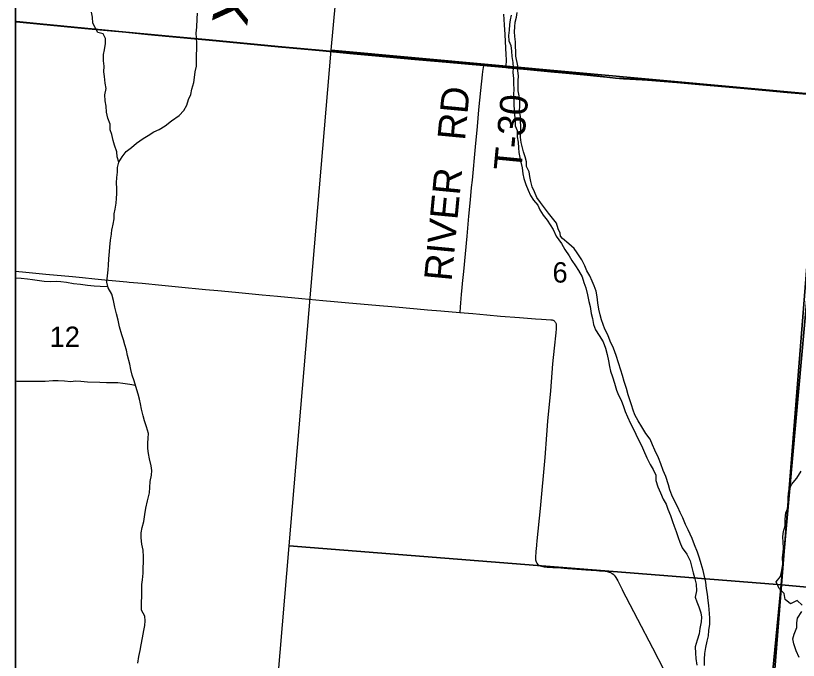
# Model space of a CAD drawing. Extents: x 0 to 1067, y 0 to 440.
# Drawn here: x 131 to 227.4, y 122 to 201.4 of the extents above; entities that cross this region are included whole.
import ezdxf

# ---------------------------------------------------------------- set-up
doc = ezdxf.new("R2010")
doc.units = 0
for name, color, linetype in [('GM_X_County_Road', 7, 'Continuous'), ('GM_X_Major_River', 7, 'Continuous'), ('GM_X_Minor_River', 7, 'Continuous'), ('GM_X_Minor_River_Text', 7, 'Continuous'), ('GM_X_Section', 7, 'Continuous'), ('GM_X_Section_Text', 7, 'Continuous'), ('GM_X_Township_Road', 7, 'Continuous'), ('GM_X_Township_Road_Text', 7, 'Continuous'), ('SH_Text', 7, 'Continuous')]:
    doc.layers.add(name, color=color, linetype=linetype)

msp = doc.modelspace()

# ---------------------------------------------------------------- linework, layer by layer
at = {"layer": 'GM_X_County_Road'}
msp.add_line((188.622, 195.247), (191.362, 194.993), dxfattribs=at)
for points in [[(131, 200.649), (131.123, 200.637), (134.011, 200.355), (139.505, 199.822), (144.57, 199.339), (147.273, 199.083), (149.897, 198.836), (154.854, 198.372), (163.342, 197.554), (166.563, 197.26), (168.841, 197.045), (172.18, 196.73), (174.869, 196.474), (180.185, 196), (184.009, 195.651), (188.622, 195.247)], [(191.362, 194.993), (191.676, 194.964), (194.011, 194.748), (196.906, 194.477), (198.761, 194.306), (200.985, 194.088), (202.579, 193.925), (204.214, 193.751), (204.904, 193.672), (205.881, 193.593), (208.153, 193.47), (208.821, 193.431), (212.462, 193.133), (214.727, 192.933), (218.886, 192.563), (221.634, 192.321), (226.053, 191.924), (227.501, 191.802), (229.802, 191.593), (230.708, 191.509)]]:
    msp.add_lwpolyline(points, dxfattribs=at)
at = {"layer": 'GM_X_Major_River'}
for points in [[(198.12, 174.21), (198.064, 174.582), (197.845, 175.14), (197.604, 175.813), (197.144, 176.421), (196.616, 177.054), (196.134, 177.709), (195.63, 178.387), (195.193, 178.994), (194.916, 179.665), (194.616, 180.292), (194.453, 180.936), (194.334, 181.557), (194.26, 182.153), (193.938, 182.803), (193.933, 183.397), (193.745, 183.997), (193.558, 184.62), (193.273, 185.771), (193.201, 186.413), (193.244, 187.12), (193.218, 187.783), (193.167, 188.379), (193.185, 188.972), (193.067, 189.616), (193.086, 190.278), (193.083, 190.941), (193.008, 191.514), (192.912, 192.111), (192.886, 192.775), (192.88, 193.346), (192.943, 193.961), (192.871, 194.603), (192.843, 195.221), (192.605, 196.416), (192.599, 196.987), (192.571, 197.582), (192.588, 198.153), (192.493, 198.819), (192.464, 199.391), (192.483, 200.03), (192.522, 200.6), (192.676, 201.189), (192.784, 201.78)], [(192.047, 201.46), (191.915, 200.87), (191.83, 200.278), (191.787, 199.594), (191.723, 198.956), (191.749, 198.27), (191.982, 197.692), (192.076, 197.026), (192.125, 196.339), (192.24, 195.605), (192.289, 194.963), (192.249, 194.371), (192.319, 193.637), (192.323, 192.997), (192.372, 192.333), (192.33, 191.672), (192.378, 190.962), (192.384, 190.391), (192.439, 189.155), (192.51, 188.468), (192.536, 187.804), (192.792, 187.225), (192.77, 186.472), (192.909, 185.782), (192.935, 185.119), (192.964, 184.524), (193.083, 183.926), (193.247, 183.327), (193.387, 182.637), (193.478, 181.88), (193.598, 181.305), (193.828, 180.59), (194.149, 179.895), (194.426, 179.246), (194.795, 178.641), (195.324, 178.031), (195.558, 177.452), (195.971, 176.8), (196.477, 176.19), (197.217, 175.025), (197.587, 174.216)], [(197.587, 174.216), (198.232, 173.327), (198.63, 172.567), (199.164, 171.781), (199.519, 171.204), (199.941, 170.558), (200.342, 169.98), (200.762, 169.197), (201.001, 168.531), (201.217, 167.842), (201.43, 166.994), (201.621, 166.192), (201.747, 165.573), (201.891, 164.704), (202.04, 164.062), (202.187, 163.352), (202.426, 162.663), (202.893, 161.993), (203.359, 161.209), (203.664, 160.405), (203.879, 159.625), (204.025, 158.869), (204.149, 158.182), (204.276, 157.587), (204.514, 156.898), (204.751, 156.095), (205.01, 155.246), (205.273, 154.648), (205.582, 154.026), (205.865, 153.245), (206.059, 152.626), (206.367, 151.958), (206.741, 151.153), (207.117, 150.462), (207.38, 149.841), (207.665, 149.22), (208.085, 148.414), (208.326, 147.839), (208.766, 146.895), (209.162, 146.09), (209.54, 145.49), (209.847, 144.777), (209.858, 144.115), (210.118, 143.334), (210.424, 142.598), (210.776, 141.839), (211.13, 141.217), (211.348, 140.597), (211.653, 139.793), (211.891, 139.058), (212.109, 138.484), (212.349, 137.841), (212.609, 137.083), (212.804, 136.509), (213.112, 135.819), (213.669, 135.033), (214.088, 134.204), (214.473, 132.76), (214.6, 132.187), (214.836, 131.361), (214.867, 130.539), (214.715, 129.743), (214.91, 129.169), (215.151, 128.572), (215.389, 127.837), (215.47, 127.265), (215.437, 126.695), (215.285, 125.876), (215.181, 125.216), (214.962, 124.467), (214.718, 123.627), (214.727, 122.851), (214.783, 122.188), (214.906, 121.365)], [(198.341, 173.922), (198.12, 174.21)], [(215.842, 121.348), (215.834, 122.124), (215.892, 122.808), (216.02, 123.559), (216.194, 124.331), (216.343, 124.991), (216.4, 125.651), (216.505, 126.403), (216.52, 127.178), (216.462, 127.75), (216.365, 128.71), (216.285, 129.35), (216.208, 130.128), (216.106, 130.814), (216.006, 131.615), (215.859, 132.302), (215.666, 133.013), (215.452, 133.838), (215.237, 134.572), (214.999, 135.284), (214.604, 136.203), (214.321, 136.984), (213.838, 138.043), (213.53, 138.71), (213.179, 139.515), (212.871, 140.159), (212.563, 140.826), (212.232, 141.471), (211.836, 142.3), (211.574, 142.989), (211.402, 143.585), (211.101, 144.595), (210.749, 145.354), (210.467, 146.181), (210.183, 146.893), (209.743, 147.859), (209.458, 148.503), (209.15, 149.193), (208.638, 149.91), (208.127, 150.741), (207.66, 151.456), (207.285, 152.193), (207.045, 152.768), (206.851, 153.433), (206.634, 154.053), (206.439, 154.673), (206.225, 155.453), (205.966, 156.302), (205.751, 157.036), (205.558, 157.724), (205.277, 158.619), (204.974, 159.537), (204.624, 160.41), (204.229, 161.285), (203.923, 162.066), (203.593, 162.756), (203.375, 163.354), (203.18, 163.928), (203.008, 164.547), (202.815, 165.212), (202.715, 166.013), (202.614, 166.745), (202.49, 167.454), (202.25, 168.098), (202.01, 168.695), (201.724, 169.316), (201.37, 169.962), (201.13, 170.559), (200.754, 171.296), (200.15, 172.168), (199.805, 172.708), (199.125, 173.274), (198.341, 173.922)]]:
    msp.add_lwpolyline(points, dxfattribs=at)
at = {"layer": 'GM_X_Minor_River'}
for points in [[(143.728, 183.34), (143.496, 183.987), (143.47, 184.627), (143.174, 185.413), (143.031, 185.989), (142.848, 186.748), (142.66, 187.325), (142.635, 188.011), (142.338, 188.774), (142.177, 189.488), (142.13, 190.22), (142.014, 190.909), (141.967, 191.642), (142.149, 192.413), (142.008, 193.057), (141.942, 193.905), (141.867, 194.478), (141.887, 195.163), (141.816, 195.828), (141.815, 196.582), (141.924, 197.195), (142.06, 197.945), (142.078, 198.584), (141.777, 199.165), (141.143, 199.298), (140.494, 200.46), (140.447, 201.193), (140.329, 201.836)], [(142.867, 175.051), (142.895, 175.136), (143.027, 175.707), (143.137, 176.343), (143.155, 176.982), (143.24, 177.551), (143.375, 178.278), (143.437, 178.847), (143.478, 179.463), (143.473, 180.08), (143.426, 180.79), (143.468, 181.451), (143.555, 182.088), (143.549, 182.66), (143.728, 183.34), (144.135, 184.013), (144.608, 184.638), (145.261, 185.144), (145.868, 185.674), (146.705, 186.265), (147.307, 186.612), (148.003, 187.071), (148.672, 187.348), (149.437, 187.804), (150.183, 188.421), (151.136, 189.078), (151.7, 189.7), (152.084, 190.351), (152.287, 191.076), (152.577, 191.661), (152.71, 192.32), (152.939, 193.135), (153.025, 193.749), (153.115, 194.478), (153.272, 195.181), (153.292, 195.866), (153.266, 196.529), (153.311, 197.305), (153.331, 197.99), (153.282, 198.654), (153.254, 199.226), (153.298, 199.956), (153.374, 201.004), (153.416, 201.688)], [(142.558, 172.314), (142.591, 172.883), (142.697, 173.724), (142.801, 174.451), (142.867, 175.051)], [(146.062, 121.624), (146.19, 122.442), (146.34, 123.168), (146.443, 123.896), (146.618, 124.736), (146.793, 125.644), (146.918, 126.257), (146.973, 126.826), (146.893, 127.42), (146.518, 128.155), (146.488, 129.045), (146.527, 129.932), (146.551, 131.299), (146.607, 131.891), (146.689, 132.687), (146.702, 133.393), (146.758, 134.03), (146.748, 134.714), (146.694, 135.558), (146.548, 136.289), (146.447, 137.066), (146.458, 137.681), (146.584, 138.34), (146.779, 139.065), (146.908, 139.951), (147.036, 140.724), (147.233, 141.609), (147.501, 142.584), (147.513, 143.245), (147.572, 144.018), (147.744, 144.767), (147.777, 145.359), (147.696, 145.93), (147.484, 146.8), (147.382, 147.462), (147.302, 148.079), (147.29, 148.717), (147.324, 149.332), (147.379, 149.923), (147.121, 150.748), (146.883, 151.481), (146.711, 152.077), (146.521, 152.9), (146.374, 153.586), (146.27, 154.158), (146.098, 154.753), (145.818, 155.692), (145.58, 156.38), (145.342, 157.091), (145.195, 157.8), (145.07, 158.44), (144.793, 159.515), (144.668, 160.178), (144.451, 160.82), (144.303, 161.438), (144.086, 162.08), (143.785, 163.065), (143.617, 163.888), (143.403, 164.666), (143.212, 165.49), (143.067, 166.29), (142.853, 167.091), (142.412, 167.873), (142.242, 168.56), (142.324, 169.333), (142.382, 170.061), (142.438, 170.653), (142.474, 171.427), (142.558, 172.314)], [(142.384, 167.987), (141.39, 168.028), (140.662, 168.064), (139.843, 168.124), (139.003, 168.275), (138.139, 168.358), (137.277, 168.533), (136.572, 168.591), (135.98, 168.624), (135.342, 168.612), (134.523, 168.626), (133.932, 168.705), (133.069, 168.834), (132.479, 168.935), (131.683, 168.995), (131, 169.048)], [(145.769, 155.836), (145.048, 155.934), (144.209, 156.085), (143.572, 156.142), (142.752, 156.134), (142.183, 156.166), (141.387, 156.203), (139.839, 156.23), (139.044, 156.335), (138.383, 156.347), (137.79, 156.289), (137.017, 156.348), (136.243, 156.384), (135.583, 156.396), (134.648, 156.321), (133.897, 156.334), (133.282, 156.322), (132.598, 156.311), (131.164, 156.336), (131, 156.358)], [(227.894, 128.767), (227.267, 129.325), (226.44, 128.929), (225.789, 129.464), (225.643, 130.218), (225.038, 130.798), (224.665, 131.625), (225.224, 132.299), (225.373, 133.026), (225.501, 133.798), (225.447, 134.642), (225.549, 135.255), (225.582, 135.824), (225.525, 136.486), (225.493, 137.238), (225.594, 137.829), (225.766, 138.555), (225.781, 139.375), (225.885, 140.125), (226.1, 140.714), (226.204, 141.441), (226.147, 142.057), (226.252, 142.853), (226.584, 143.622), (227.213, 144.409), (227.752, 145.265)], [(227.508, 122.326), (227.158, 123.129), (226.854, 124), (226.728, 124.595), (226.875, 125.207), (227.208, 126.022), (227.241, 126.591), (227.32, 127.159), (227.835, 127.971)]]:
    msp.add_lwpolyline(points, dxfattribs=at)
at = {"layer": 'GM_X_Section'}
for points in [[(175.453, 257.739), (235.406, 252.097), (230.143, 191.616), (169.87, 197.127)], [(169.87, 197.127), (230.143, 191.616), (225.317, 131.247), (164.671, 136.077)], [(230.143, 191.616), (293.305, 184.745), (289.359, 125.481), (225.317, 131.247)], [(164.671, 136.077), (225.317, 131.247), (220.613, 71.485), (159.707, 77.206)], [(225.317, 131.247), (289.359, 125.481), (286.308, 90.531), (282.115, 64.529), (220.613, 71.485)]]:
    msp.add_lwpolyline(points, close=True, dxfattribs=at)
at = {"layer": 'GM_X_Township_Road'}
msp.add_line((191.362, 194.993), (188.622, 195.247), dxfattribs=at)
for points in [[(131, 425.107), (131, 200.68), (131.11, 200.669), (133.997, 200.387), (139.492, 199.854), (144.557, 199.371), (147.26, 199.115), (149.884, 198.868), (154.84, 198.405), (163.329, 197.586), (166.549, 197.292), (168.828, 197.078), (172.167, 196.762), (174.855, 196.506), (180.172, 196.033), (183.996, 195.683), (188.609, 195.279), (191.348, 195.025), (191.662, 194.996), (193.997, 194.781), (196.892, 194.51), (198.747, 194.339), (200.971, 194.12), (202.566, 193.957), (204.2, 193.783), (204.89, 193.704), (205.867, 193.625), (208.139, 193.502), (208.808, 193.463), (212.448, 193.165), (214.714, 192.965), (218.872, 192.595), (221.62, 192.353), (226.039, 191.956), (227.488, 191.835)], [(191.089, 201.575), (191.162, 200.258), (191.236, 199.051), (191.35, 197.368), (191.374, 196.608), (191.404, 195.962), (191.409, 195.809), (191.404, 195.612), (191.395, 195.448), (191.384, 195.306), (191.374, 195.168), (191.362, 194.993)], [(227.488, 191.835), (226.039, 191.956), (221.62, 192.353), (218.872, 192.595), (214.714, 192.965), (212.448, 193.165), (208.808, 193.463), (208.139, 193.502), (205.867, 193.625), (204.89, 193.704), (204.2, 193.783), (202.566, 193.957), (200.971, 194.12), (198.747, 194.339), (196.892, 194.51), (193.997, 194.781), (191.662, 194.996), (191.348, 195.025), (188.609, 195.279), (183.996, 195.683), (180.172, 196.033), (174.855, 196.506), (172.167, 196.762), (168.828, 197.078), (166.549, 197.292), (163.329, 197.586), (154.84, 198.405), (149.884, 198.868), (147.26, 199.115), (144.557, 199.371), (139.492, 199.854), (133.997, 200.387), (131.11, 200.669), (131, 200.68), (131, 17.107)], [(188.622, 195.247), (188.509, 194.52), (188.45, 194.114), (188.255, 192.186), (188.019, 189.774), (187.831, 187.732), (187.601, 185.245), (187.215, 181.124), (187.127, 180.234), (186.986, 178.712), (186.797, 176.67), (186.577, 174.22), (186.379, 172.029), (186.166, 169.877), (186.008, 168.394), (185.953, 167.837), (185.888, 167.086), (185.836, 166.509), (185.792, 166.006), (185.759, 165.484), (185.714, 164.824)], [(230.694, 191.542), (225.269, 130.852), (222.35, 100.868), (216.022, 17.107), (539, 17.107)], [(222.35, 100.868), (225.269, 130.852), (230.694, 191.542)], [(131, 169.891), (132.267, 169.778), (134.717, 169.553), (138.02, 169.238), (139.241, 169.119), (140.744, 168.973), (141.973, 168.854), (143.806, 168.665), (144.677, 168.586)], [(144.677, 168.586), (144.968, 168.559), (146.578, 168.413), (149.003, 168.181), (151.076, 167.983), (154.383, 167.667), (155.904, 167.525), (158.096, 167.314), (161.359, 167.001), (163.253, 166.831), (166.263, 166.547), (168.82, 166.306), (170.231, 166.181), (171.604, 166.055), (175.799, 165.669), (177.322, 165.545), (180.451, 165.27), (181.721, 165.159), (183.375, 165.02), (185.714, 164.824)], [(185.714, 164.824), (187.325, 164.678), (189.05, 164.522), (190.722, 164.381), (193.062, 164.188), (195.023, 164.039), (195.786, 163.981), (196.912, 163.913), (196.999, 163.906), (197.083, 163.896), (197.155, 163.88), (197.217, 163.86), (197.29, 163.824), (197.346, 163.784), (197.388, 163.748), (197.433, 163.701), (197.473, 163.644), (197.511, 163.579), (197.544, 163.5), (197.567, 163.421), (197.585, 163.341), (197.594, 163.201), (197.56, 162.815), (197.518, 162.332), (197.333, 160.439), (197.146, 158.509), (196.862, 155.166), (196.524, 151.415), (196.4, 149.743), (196.179, 146.955), (195.603, 140.681), (195.215, 136.673), (195.168, 136.19), (195.11, 135.671), (195.085, 135.447), (195.059, 135.186), (195.034, 134.846), (195.022, 134.669), (195.028, 134.485), (195.039, 134.359), (195.068, 134.221), (195.108, 134.1), (195.2, 133.922), (195.321, 133.79), (195.453, 133.693), (195.602, 133.612), (195.775, 133.555), (195.93, 133.515), (196.102, 133.487), (196.477, 133.451), (196.775, 133.436), (197.185, 133.413), (197.707, 133.383), (199.009, 133.294), (201.213, 133.134), (202.542, 133.038), (202.914, 133.007), (203.178, 132.99), (203.624, 132.938), (203.877, 132.895), (204.097, 132.837), (204.274, 132.774), (204.436, 132.687), (204.585, 132.579), (204.711, 132.458), (204.833, 132.302), (204.941, 132.154), (205.169, 131.766), (205.303, 131.497), (205.39, 131.332), (205.587, 130.93), (205.71, 130.7), (205.892, 130.332), (206.161, 129.799), (207.594, 127.056), (209.435, 123.518), (210.891, 120.703)]]:
    msp.add_lwpolyline(points, dxfattribs=at)
at = {"layer": 'SH_Text'}
msp.add_lwpolyline([(131, 425.107), (539, 425.107), (539, 17.107), (131, 17.107)], close=True, dxfattribs=at)

# ---------------------------------------------------------------- texts
at = {"layer": 'GM_X_Minor_River_Text'}
msp.add_text('Creek', height=5.6788, rotation=260.08523, dxfattribs=at).set_placement((158.681, 220.756))
at = {"layer": 'GM_X_Section_Text'}
for s, height, p in [('6', 2.511, (197.129, 168.501)), ('12', 2.5114, (135.179, 160.57))]:
    msp.add_text(s, height=height, rotation=0.00001, dxfattribs=at).set_placement(p)
at = {"layer": 'GM_X_Township_Road_Text'}
for s, rotation, p in [('RD', 84.6287, (186.343, 185.936)), ('T-30', 84.50356, (193.271, 182.176)), ('RIVER', 84.57889, (184.694, 168.597))]:
    msp.add_text(s, height=3.4091, rotation=rotation, dxfattribs=at).set_placement(p)

doc.saveas('drawing.dxf')
